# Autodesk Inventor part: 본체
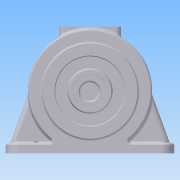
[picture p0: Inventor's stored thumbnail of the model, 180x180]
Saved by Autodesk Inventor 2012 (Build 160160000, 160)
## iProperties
Created: 2015-06
Part Number: 본체
Material: 알루미늄-6061
Document SubType Name: Modeling
Designer: User
Density: 2.71 g/cm^3
Author: User
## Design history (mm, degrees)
sketch "스케치1"
  geometry: C1 r 85 at (0, 0); 2 further points
  constraints: 2 coincident, 1 centre point
  dimensions: "d0" = 170 diameter of C1
extrude "돌출1" new body sketch "스케치1" stored distance "d1" = 118; taper "d2" = 0 deg
sketch "스케치2"
  geometry: C1 r 85 at (0, 0) reference; C2 r 65 at (0, 0)
  constraints: 1 centre point, 1 coincident
  dimensions: "d3" = 130 diameter of C2
extrude "돌출2" join sketch "스케치2" distance "d4" = 13; taper "d5" = 0 deg
sketch "스케치3"
  geometry: C1 r 85 at (0, 0) reference; C2 r 65 at (0, 0)
  constraints: 1 centre point, 1 coincident
  dimensions: "d6" = 130 diameter of C2
extrude "돌출3" join sketch "스케치3" distance "d7" = 3; taper "d8" = 0 deg
sketch "스케치5"
  geometry: L1 (85, -59)-(-85, -59) reference; L2 (-85, 59)-(85, 59) reference; L3 (-74, 51)-(-31, 51); L4 (0, -51)-(-74, -51); L5 (-77, -48)-(-77, 48); L6 (-85, -59)-(-85, 59) reference; L7 (85, -59)-(85, 59) reference; L8 (0, 61.5)-(0, -51); L9 (-31, 51)-(-29.368, 47.5); L10 (-29.368, 47.5)-(-23.5, 47.5); L11 (-23.5, 47.5)-(-23.5, 61.5); L12 (-23.5, 61.5)-(0, 61.5); A1 r 3 centre (-74, 48) between (-74, 51) and (-77, 48); A2 r 3 centre (-74, -48) between (-77, -48) and (-74, -51); 6 further points
  constraints: 16 end point, 6 point on line, 4 point on circle, 4 tangent, 3 perpendicular, 2 centre point, 1 coincident, 1 equal radius, 1 horizontal, 1 horizontal alignment, 1 midpoint, 1 parallel, 1 vertical alignment
  dimensions: "d11" = 8 distance between parallel lines of L2 L3; "d13" = 8 distance between parallel lines of L6 L5; "d100" = 115 deg angle of L3 L9; "d101" = 62 diameter of L3.end L8; "d102" = 3 radius of A1; "d104" = 14 distance between parallel lines of L10 L12; "d105" = 47 diameter of L11 L8; "d106" = 3.5 distance between parallel lines of L10 L3
revolve "회전1" sketch "스케치5" stored, may be unused: angle "d14" = 90 deg
node "작업 평면3"
sketch "스케치6"
  geometry: L1 (-42.5, 42.5)-(42.5, 42.5); L2 (42.5, 42.5)-(42.5, -42.5); L3 (42.5, -42.5)-(-42.5, -42.5); L4 (-42.5, -42.5)-(-42.5, 42.5); 3 further points
  constraints: 8 end point, 2 midpoint, 2 parallel, 1 horizontal, 1 horizontal alignment, 1 perpendicular, 1 vertical alignment
  dimensions: "d28" = 85 distance of L2.end L3.end; "d29" = 85 distance of L3.end L1.start
extrude "돌출4" join sketch "스케치6" stored distance "d17" = 3; taper "d18" = 0 deg
hole "구멍1" diameter "d21" = 95; stored, may be unused: countersink angle "d25" = 90 deg, drill point angle "d27" = 118 deg; dims "d19" = 10, "d20" = 10, "d22" = 6, "d23" = 4, "d24" = 2, "d26" = 50
fillet "모깎기1" dims "d30" = 7
sketch "스케치7"
  geometry: 2 further points
  constraints: 1 coincident
hole "구멍2" sketch "스케치7" at (0, 0) diameter "d31" = 71; stored, may be unused: countersink angle "d35" = 90 deg, drill point angle "d37" = 50 deg; dims "d32" = 6, "d33" = 4, "d34" = 2, "d36" = 50
hole "구멍3" diameter "d40" = 3.242; stored, may be unused: countersink angle "d44" = 90 deg, drill point angle "d46" = 50 deg; dims "d38" = 10, "d39" = 10, "d41" = 10, "d42" = 4, "d43" = 2, "d45" = 13
sketch "스케치8"
  geometry: C1 r 47.5 at (0, 0) reference; 1 further point
  constraints: 1 horizontal alignment
  dimensions: "d53" = 55 distance of C1.centre point (-55, 0)
hole "구멍4" sketch "스케치8" at (-55, 0) diameter "d54" = 3.242; stored, may be unused: countersink angle "d58" = 90 deg, drill point angle "d60" = 50 deg; dims "d55" = 10, "d56" = 4, "d57" = 2, "d59" = 13
node "작업 평면4"
sketch "스케치9"
  geometry: L1 (115, 59)-(-115, 59); L2 (-115, 59)-(-115, -59); L3 (-115, -59)-(115, -59); L4 (115, -59)-(115, 59); 3 further points
  constraints: 8 end point, 2 midpoint, 2 parallel, 1 horizontal, 1 horizontal alignment, 1 perpendicular, 1 vertical alignment
  dimensions: "d65" = 118 distance of L3.end L1.start; "d66" = 230 distance of L1.start L1.end
extrude "돌출5" join sketch "스케치9" distance "d67" = 14; taper "d68" = 0 deg
fillet "모깎기2" dims "d69" = 18
sketch "스케치10"
  geometry: L1 (-32, 81)-(-32, 97); L2 (-50, 81)-(-50, 97); A1 r 18 centre (-41, 97) between (-41, 115) and (-59, 97) reference; A2 r 9 centre (-41, 97) between (-32, 97) and (-50, 97); A3 r 9 centre (-41, 81) between (-50, 81) and (-32, 81); 1 further point
  constraints: 4 end point, 4 point on circle, 4 tangent, 2 centre point, 1 coincident, 1 vertical alignment
  dimensions: "d70" = 18 diameter of A2; "d71" = 18 diameter of A3; "d72" = 16 distance of A1.centre A3.centre
extrude "돌출7" join sketch "스케치10" distance "d78" = 3; taper "d79" = 0 deg
sketch "스케치11"
  geometry: L1 (-50, 81)-(-50, 97) reference; L2 (-32, 97)-(-32, 81) reference; L3 (-45, 97)-(-45, 81); L4 (-37, 81)-(-37, 97); A1 r 9 centre (-41, 81) between (-50, 81) and (-32, 81) reference; A2 r 9 centre (-41, 97) between (-32, 97) and (-50, 97) reference; A3 r 4 centre (-41, 81) between (-45, 81) and (-37, 81); A4 r 4 centre (-41, 97) between (-37, 97) and (-45, 97); 1 further point
  constraints: 4 end point, 4 point on circle, 2 centre point, 3 other
  dimensions: "d80" = 5 distance between parallel lines of L2 L4
extrude "돌출8" cut sketch "스케치11" stored distance "d81" = 3; taper "d82" = 0 deg
sketch "스케치12"
  geometry: L1 (-71, -109)-(-4.703, -84.87); L2 (-71, -115)-(-85, -115) reference; L3 (-71, -97)-(-71, -115) reference; A1 r 85 centre (0, 0) between (-71, -46.733) and (-71, 46.733) reference; 1 further point
  constraints: 2 end point, 1 point on circle, 1 point on line
  dimensions: "d90" = 6 distance from line of L2 L1.start; "d91" = 110 deg angle of L3 L1
feature "리브1" sketch "스케치12" dims "d92" = 1, "d93" = 15, "d94" = 0, "d95" = 0, "d96" = 1, "d97" = 1
fillet "모깎기3" dims "d98" = 7.5
fillet "모깎기4" dims "d99" = 3
hole "구멍5" diameter "d109" = 30; stored, may be unused: countersink angle "d113" = 90 deg, drill point angle "d115" = 0 deg; dims "d107" = 10, "d108" = 10, "d110" = 10, "d111" = 4, "d112" = 2, "d114" = 3
fillet "모깎기5" dims "d116" = 0.3
fillet "모깎기6" dims "d117" = 3
fillet "모깎기9" dims "d120" = 3
fillet "모깎기10" dims "d121" = 3
fillet "모깎기11" dims "d122" = 3
chamfer "모따기1" distance "d123" = 1; stored, may be unused: second distance "d124" = 2, angle "d125" = 45 deg
sketch "스케치13"
  geometry: L1 (0, 0)-(35.923, 77.036); L2 (0, 0)-(85, 0); A1 r 85 centre (0, 0) between (-65.682, -53.953) and (-65.682, 53.953) reference; 1 further point
  constraints: 4 end point, 1 equal length, 1 horizontal, 1 point on circle
  dimensions: "d126" = 65 deg angle of L2 L1
node "작업 평면5"
sketch "스케치14"
  geometry: L1 (-7, -41)-(-7, 41); L2 (-7, 41)-(7, 41); L3 (7, 41)-(7, -41); L4 (7, -41)-(-7, -41); L5 (7, -41)-(-7, 41); L6 (-7, -41)-(-0.002, 0.011); L7 (-0.002, 0.011)-(7, 41); 4 further points
  constraints: 6 end point, 3 midpoint, 1 coincident, 1 horizontal alignment, 1 point on line, 1 vertical alignment, 2 other
  dimensions: "d127" = 82 distance of L2.end L3.end; "d128" = 14 distance of L1.end L2.end
feature "엠보싱1" sketch "스케치14" dims "d129" = 0.5, "d130" = 0
fillet "모깎기12" dims "d131" = 3
node "솔리드1"
pattern_linear "직사각형 패턴1" dims "d49" = 71, "d52" = 71
pattern_circular "원형 패턴1" dims angle "d62" = 360 deg
pattern_linear "직사각형 패턴2" dims "d85" = 178, "d88" = 82
mirror "대칭1"
node "투영된 루프1"
other parameters: "d15" = 88, "d64" = -85
